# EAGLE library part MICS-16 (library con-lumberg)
CONNECTOR
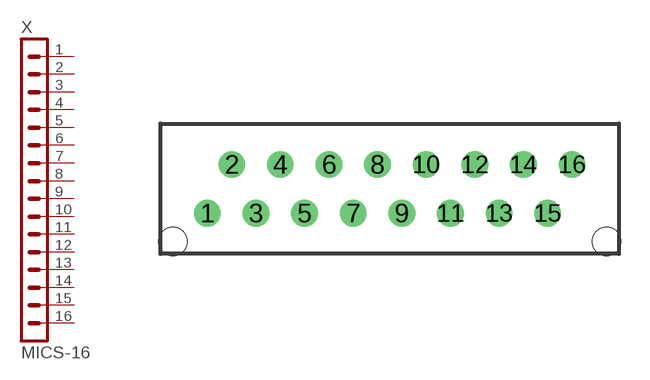
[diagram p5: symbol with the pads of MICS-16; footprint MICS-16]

Designator prefix X

## MICS-16 (OC_FARNELL: unknown; OC_NEWARK: unknown)  [MICS-16]
1  1  pas
2  2  pas
3  3  pas
4  4  pas
5  5  pas
6  6  pas
7  7  pas
8  8  pas
9  9  pas
10  10  pas
11  11  pas
12  12  pas
13  13  pas
14  14  pas
15  15  pas
16  16  pas

## Footprint MICS-16 (pad centres in mm)
CONNECTOR
drill 0.85 pad 1.397 round: 1 -9.525,-1.27; 2 -8.255,1.27; 3 -6.985,-1.27; 4 -5.715,1.27; 5 -4.445,-1.27; 6 -3.175,1.27; 7 -1.905,-1.27; 8 -0.635,1.27; 9 0.635,-1.27; 10 1.905,1.27; 11 3.175,-1.27; 12 4.445,1.27; 13 5.715,-1.27; 14 6.985,1.27; 15 8.255,-1.27; 16 9.525,1.27
hole 1.5 at 11.325,-2.75
hole 1.5 at -11.325,-2.75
